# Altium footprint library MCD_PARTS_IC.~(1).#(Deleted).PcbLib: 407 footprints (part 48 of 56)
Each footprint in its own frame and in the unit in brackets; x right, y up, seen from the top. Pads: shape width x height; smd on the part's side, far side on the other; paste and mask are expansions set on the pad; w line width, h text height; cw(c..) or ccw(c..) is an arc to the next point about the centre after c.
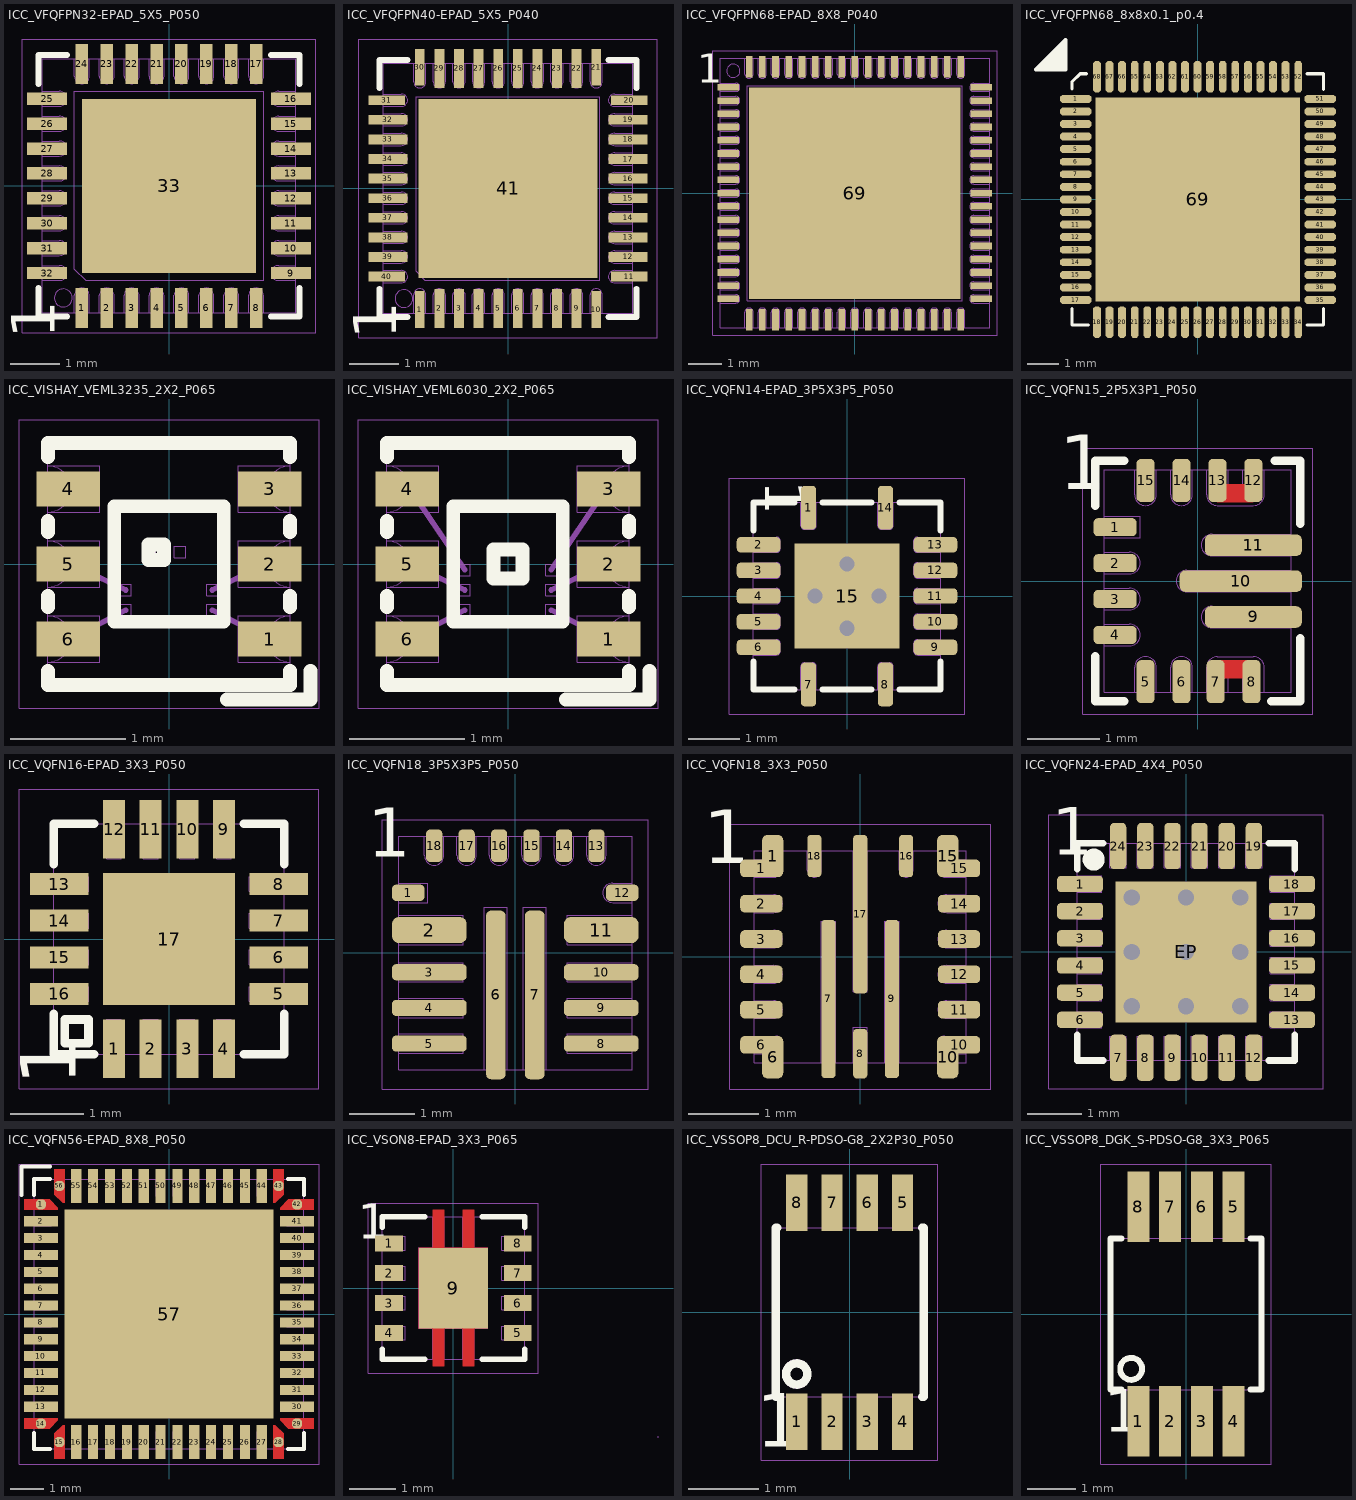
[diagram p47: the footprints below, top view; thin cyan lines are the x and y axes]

## ICC_VFQFPN32-EPAD_5X5_P050 [mm]
height 1
pads (33):
  rect 0.25x0.8 smd mask+0.05: 1(-1.75,-2.45) 2(-1.25,-2.45) 3(-0.75,-2.45) 4(-0.25,-2.45) 5(0.25,-2.45) 6(0.75,-2.45) 7(1.25,-2.45) 8(1.75,-2.45) 17(1.75,2.45) 18(1.25,2.45) 19(0.75,2.45) 20(0.25,2.45) 21(-0.25,2.45) 22(-0.75,2.45) 23(-1.25,2.45) 24(-1.75,2.45)
  rect 0.8x0.25 smd mask+0.05: 9(2.45,-1.75) 10(2.45,-1.25) 11(2.45,-0.75) 12(2.45,-0.25) 13(2.45,0.25) 14(2.45,0.75) 15(2.45,1.25) 16(2.45,1.75) 25(-2.45,1.75) 26(-2.45,1.25) 27(-2.45,0.75) 28(-2.45,0.25) 29(-2.45,-0.25) 30(-2.45,-0.75) 31(-2.45,-1.25) 32(-2.45,-1.75)
  rect 3.5x3.5 smd mask+0.05: 33(0,0)
Top Overlay:
  lines w0.12: -2.625,-2.05 -2.625,-2.625 -2.05,-2.625 ; -2.625,2.05 -2.625,2.625 -2.05,2.625 ; 2.05,-2.625 2.625,-2.625 2.625,-2.05 ; 2.05,2.625 2.625,2.625 2.625,2.05
  text "1" at -2,-3.075 h1.5
M14-Top Assembly:
  circle w0.01: c-2.125,-2.25 r0.18
  lines w0.01: -2.55,-1.9 -2.2,-1.9 ccw(c-2.2,-1.75) -2.05,-1.75 ccw(c-2.2,-1.75) -2.2,-1.6 -2.55,-1.6 ; -2.55,-1.4 -2.2,-1.4 ccw(c-2.2,-1.25) -2.05,-1.25 ccw(c-2.2,-1.25) -2.2,-1.1 -2.55,-1.1 ; -2.55,-0.9 -2.2,-0.9 ccw(c-2.2,-0.75) -2.05,-0.75 ccw(c-2.2,-0.75) -2.2,-0.6 -2.55,-0.6 ; -2.55,-0.4 -2.2,-0.4 ccw(c-2.2,-0.25) -2.05,-0.25 ccw(c-2.2,-0.25) -2.2,-0.1 -2.55,-0.1 ; -2.55,0.1 -2.2,0.1 ccw(c-2.2,0.25) -2.05,0.25 ccw(c-2.2,0.25) -2.2,0.4 -2.55,0.4 ; -2.55,0.6 -2.2,0.6 ccw(c-2.2,0.75) -2.05,0.75 ccw(c-2.2,0.75) -2.2,0.9 -2.55,0.9 ; -2.55,1.1 -2.2,1.1 ccw(c-2.2,1.25) -2.05,1.25 ccw(c-2.2,1.25) -2.2,1.4 -2.55,1.4 ; -2.55,1.6 -2.2,1.6 ccw(c-2.2,1.75) -2.05,1.75 ccw(c-2.2,1.75) -2.2,1.9 -2.55,1.9 ; -1.9,-2.55 -1.9,-2.2 cw(c-1.75,-2.2) -1.75,-2.05 cw(c-1.75,-2.2) -1.6,-2.2 -1.6,-2.55 ; -1.9,2.55 -1.9,2.2 ccw(c-1.75,2.2) -1.75,2.05 ccw(c-1.75,2.2) -1.6,2.2 -1.6,2.55 ; -1.4,-2.55 -1.4,-2.2 cw(c-1.25,-2.2) -1.25,-2.05 cw(c-1.25,-2.2) -1.1,-2.2 -1.1,-2.55 ; -1.4,2.55 -1.4,2.2 ccw(c-1.25,2.2) -1.25,2.05 ccw(c-1.25,2.2) -1.1,2.2 -1.1,2.55 ; -0.9,-2.55 -0.9,-2.2 cw(c-0.75,-2.2) -0.75,-2.05 cw(c-0.75,-2.2) -0.6,-2.2 -0.6,-2.55 ; -0.9,2.55 -0.9,2.2 ccw(c-0.75,2.2) -0.75,2.05 ccw(c-0.75,2.2) -0.6,2.2 -0.6,2.55 ; -0.4,-2.55 -0.4,-2.2 cw(c-0.25,-2.2) -0.25,-2.05 cw(c-0.25,-2.2) -0.1,-2.2 -0.1,-2.55 ; -0.4,2.55 -0.4,2.2 ccw(c-0.25,2.2) -0.25,2.05 ccw(c-0.25,2.2) -0.1,2.2 -0.1,2.55 ; 0.1,-2.55 0.1,-2.2 cw(c0.25,-2.2) 0.25,-2.05 cw(c0.25,-2.2) 0.4,-2.2 0.4,-2.55 ; 0.1,2.55 0.1,2.2 ccw(c0.25,2.2) 0.25,2.05 ccw(c0.25,2.2) 0.4,2.2 0.4,2.55 ; 0.6,-2.55 0.6,-2.2 cw(c0.75,-2.2) 0.75,-2.05 cw(c0.75,-2.2) 0.9,-2.2 0.9,-2.55 ; 0.6,2.55 0.6,2.2 ccw(c0.75,2.2) 0.75,2.05 ccw(c0.75,2.2) 0.9,2.2 0.9,2.55 ; 1.1,-2.55 1.1,-2.2 cw(c1.25,-2.2) 1.25,-2.05 cw(c1.25,-2.2) 1.4,-2.2 1.4,-2.55 ; 1.1,2.55 1.1,2.2 ccw(c1.25,2.2) 1.25,2.05 ccw(c1.25,2.2) 1.4,2.2 1.4,2.55 ; 1.6,-2.55 1.6,-2.2 cw(c1.75,-2.2) 1.75,-2.05 cw(c1.75,-2.2) 1.9,-2.2 1.9,-2.55 ; 1.6,2.55 1.6,2.2 ccw(c1.75,2.2) 1.75,2.05 ccw(c1.75,2.2) 1.9,2.2 1.9,2.55 ; 2.55,-1.9 2.2,-1.9 cw(c2.2,-1.75) 2.05,-1.75 cw(c2.2,-1.75) 2.2,-1.6 2.55,-1.6 ; 2.55,-1.4 2.2,-1.4 cw(c2.2,-1.25) 2.05,-1.25 cw(c2.2,-1.25) 2.2,-1.1 2.55,-1.1 ; 2.55,-0.9 2.2,-0.9 cw(c2.2,-0.75) 2.05,-0.75 cw(c2.2,-0.75) 2.2,-0.6 2.55,-0.6 ; 2.55,-0.4 2.2,-0.4 cw(c2.2,-0.25) 2.05,-0.25 cw(c2.2,-0.25) 2.2,-0.1 2.55,-0.1 ; 2.55,0.1 2.2,0.1 cw(c2.2,0.25) 2.05,0.25 cw(c2.2,0.25) 2.2,0.4 2.55,0.4 ; 2.55,0.6 2.2,0.6 cw(c2.2,0.75) 2.05,0.75 cw(c2.2,0.75) 2.2,0.9 2.55,0.9 ; 2.55,1.1 2.2,1.1 cw(c2.2,1.25) 2.05,1.25 cw(c2.2,1.25) 2.2,1.4 2.55,1.4 ; 2.55,1.6 2.2,1.6 cw(c2.2,1.75) 2.05,1.75 cw(c2.2,1.75) 2.2,1.9 2.55,1.9 ; -2.55,-2.55 -2.55,2.55 2.55,2.55 2.55,-2.55 -2.55,-2.55 ; -1.9,-1.67 -1.9,1.9 1.9,1.9 1.9,-1.9 -1.67,-1.9 -1.9,-1.67
  text "33" at -0.275,-0.15 h0.5
  text "32" at -2.45,-1.525 h0.5
  text "25" at -2.45,2 h0.5
  text "24" at -1.975,2.175 h0.5
  text "17" at 1.55,2.15 h0.5
  text "16" at 2.45,1.575 h0.5
  text "9" at 2.45,-1.85 h0.5
  text "8" at 1.65,-2.475 h0.5
  text "1" at -1.8,-2.475 h0.5
  text "'.Designator'" at -2,-0.5 h0.75
M16-Top Courtyard:
  lines w0.01: -2.95,-2.95 2.95,-2.95 2.95,2.95 -2.95,2.95 -2.95,-2.95
3D body "QFN32-EPAD_5X5_P050.STEP": height 0.9, standoff -0.03, extent -2.5,-2.5 2.5,2.5

## ICC_VFQFPN40-EPAD_5X5_P040 [mm]
height 1
pads (41):
  rect 0.2x0.75 smd mask+0.05: 1(-1.8,-2.475) 10(1.8,-2.475) 21(1.8,2.475) 30(-1.8,2.475)
  rect 0.2x0.8 smd mask+0.05: 2(-1.4,-2.45) 3(-1,-2.45) 4(-0.6,-2.45) 5(-0.2,-2.45) 6(0.2,-2.45) 7(0.6,-2.45) 8(1,-2.45) 9(1.4,-2.45) 22(1.4,2.45) 23(1,2.45) 24(0.6,2.45) 25(0.2,2.45) 26(-0.2,2.45) 27(-0.6,2.45) 28(-1,2.45) 29(-1.4,2.45)
  rect 0.75x0.2 smd mask+0.05: 11(2.475,-1.8) 20(2.475,1.8) 31(-2.475,1.8) 40(-2.475,-1.8)
  rect 0.8x0.2 smd mask+0.05: 12(2.45,-1.4) 13(2.45,-1) 14(2.45,-0.6) 15(2.45,-0.2) 16(2.45,0.2) 17(2.45,0.6) 18(2.45,1) 19(2.45,1.4) 32(-2.45,1.4) 33(-2.45,1) 34(-2.45,0.6) 35(-2.45,0.2) 36(-2.45,-0.2) 37(-2.45,-0.6) 38(-2.45,-1) 39(-2.45,-1.4)
  rect 3.65x3.65 smd mask+0.05: 41(0,0)
Top Overlay:
  lines w0.12: -2.625,-2.05 -2.625,-2.625 -2.05,-2.625 ; -2.625,2.05 -2.625,2.625 -2.05,2.625 ; 2.05,-2.625 2.625,-2.625 2.625,-2.05 ; 2.05,2.625 2.625,2.625 2.625,2.05
  text "1" at -2,-3.075 h1.5
M14-Top Assembly:
  drawing of 170 lines, arcs and shapes, not listed
  text "31" at -2.45,2 h0.5
  text "'.Designator'" at -2,-0.5 h0.75
  text "1" at -1.85,-2.475 h0.5
  text "10" at 1.55,-2.475 h0.5
  text "11" at 2.475,-2 h0.5
  text "20" at 2.45,1.575 h0.5
  text "21" at 1.6,2.15 h0.5
  text "30" at -2.05,2.175 h0.5
  text "40" at -2.475,-1.55 h0.5
  text "41" at -0.275,-0.15 h0.5
M16-Top Courtyard:
  lines w0.01: -3.05,-3.05 -3.05,3.05 3.05,3.05 3.05,-3.05 -3.05,-3.05
3D body "User Library-QFN40_500_500_090_360P040.STEP": height 0.9, standoff 0, extent -2.505,-2.505 2.505,2.505

## ICC_VFQFPN68-EPAD_8X8_P040 [mm]
height 1
pads (69):
  rect 0.65x0.2 smd mask+0.05: 1(-3.825,3.2) 2(-3.825,2.8) 3(-3.825,2.4) 4(-3.825,2) 5(-3.825,1.6) 6(-3.825,1.2) 7(-3.825,0.8) 8(-3.825,0.4) 9(-3.825,0) 10(-3.825,-0.4) 11(-3.825,-0.8) 12(-3.825,-1.2) 13(-3.825,-1.6) 14(-3.825,-2) 15(-3.825,-2.4) 16(-3.825,-2.8) 17(-3.825,-3.2) 35(3.825,-3.2) 36(3.825,-2.8) 37(3.825,-2.4) 38(3.825,-2) 39(3.825,-1.6) 40(3.825,-1.2) 41(3.825,-0.8) 42(3.825,-0.4) 43(3.825,0) 44(3.825,0.4) 45(3.825,0.8) 46(3.825,1.2) 47(3.825,1.6) 48(3.825,2) 49(3.825,2.4) 50(3.825,2.8) 51(3.825,3.2)
  rect 0.2x0.65 smd mask+0.05: 18(-3.2,-3.825) 19(-2.8,-3.825) 20(-2.4,-3.825) 21(-2,-3.825) 22(-1.6,-3.825) 23(-1.2,-3.825) 24(-0.8,-3.825) 25(-0.4,-3.825) 26(0,-3.825) 27(0.4,-3.825) 28(0.8,-3.825) 29(1.2,-3.825) 30(1.6,-3.825) 31(2,-3.825) 32(2.4,-3.825) 33(2.8,-3.825) 34(3.2,-3.825) 52(3.2,3.825) 53(2.8,3.825) 54(2.4,3.825) 55(2,3.825) 56(1.6,3.825) 57(1.2,3.825) 58(0.8,3.825) 59(0.4,3.825) 60(0,3.825) 61(-0.4,3.825) 62(-0.8,3.825) 63(-1.2,3.825) 64(-1.6,3.825) 65(-2,3.825) 66(-2.4,3.825) 67(-2.8,3.825) 68(-3.2,3.825)
  rect 6.4x6.4 smd mask+0.05: 69(0,0)
Top Overlay:
  text "1" at -4.775,3.05 h1.5
M14-Top Assembly:
  drawing of 281 lines, arcs and shapes, not listed
  text "69" at -0.325,-0.2 h0.65
  text "1" at -3.837,3.075 h0.65
  text "17" at -3.975,-3.45 h0.65
  text "34" at 2.9,-4 h0.65
  text "18" at -3.55,-3.975 h0.65
  text "'.Designator'" at -2,0 h0.75
  text "35" at 3.425,-3.425 h0.65
  text "51" at 3.425,3 h0.65
  text "52" at 2.925,3.6 h0.65
  text "68" at -3.475,3.55 h0.65
M16-Top Courtyard:
  lines w0.01: -4.3,-4.3 -4.3,4.3 4.3,4.3 4.3,-4.3 -4.3,-4.3
3D body: height 1, standoff 0, extent -4.075,-4.075 4.075,4.075
3D body: height 1.1, standoff 1, extent -3.873,3.5 -3.475,3.9

## ICC_VFQFPN68_8x8x0.1_p0.4 [mm]
pads (69):
  oct 1x0.25 smd mask+0.04: 1(-3.878,3.2) 2(-3.878,2.8) 3(-3.878,2.4) 4(-3.878,2) 5(-3.878,1.6) 6(-3.878,1.2) 7(-3.878,0.8) 8(-3.878,0.4) 9(-3.878,0) 10(-3.878,-0.4) 11(-3.878,-0.8) 12(-3.878,-1.2) 13(-3.878,-1.6) 14(-3.878,-2) 15(-3.878,-2.4) 16(-3.878,-2.8) 17(-3.878,-3.2) 35(3.903,-3.2) 36(3.903,-2.8) 37(3.903,-2.4) 38(3.903,-2) 39(3.903,-1.6) 40(3.903,-1.2) 41(3.903,-0.8) 42(3.903,-0.4) 43(3.903,0) 44(3.903,0.4) 45(3.903,0.8) 46(3.903,1.2) 47(3.903,1.6) 48(3.903,2) 49(3.903,2.4) 50(3.903,2.8) 51(3.903,3.2)
  oct 0.25x1 smd mask+0.04: 18(-3.2,-3.903) 19(-2.8,-3.903) 20(-2.4,-3.903) 21(-2,-3.903) 22(-1.6,-3.903) 23(-1.2,-3.903) 24(-0.8,-3.903) 25(-0.4,-3.903) 26(0,-3.903) 27(0.4,-3.903) 28(0.8,-3.903) 29(1.2,-3.903) 30(1.6,-3.903) 31(2,-3.903) 32(2.4,-3.903) 33(2.8,-3.903) 34(3.2,-3.903) 52(3.2,3.903) 53(2.8,3.903) 54(2.4,3.903) 55(2,3.903) 56(1.6,3.903) 57(1.2,3.903) 58(0.8,3.903) 59(0.4,3.903) 60(0,3.903) 61(-0.4,3.903) 62(-0.8,3.903) 63(-1.2,3.903) 64(-1.6,3.903) 65(-2,3.903) 66(-2.4,3.903) 67(-2.8,3.903) 68(-3.2,3.903)
  rect 6.5x6.5 smd paste-5 mask-0.01: 69(0,0)
Top Overlay:
  lines w0.1: -4,-3.467 -4,-4 -3.48,-4 ; -4,3.518 -4,3.734 -3.734,4 -3.531,4 ; 3.48,-4 4,-4 4,-3.467 ; 3.48,4 4,4 4,3.493
  lines w0.127: -4.451,4.613 -5.141,4.126 ; -5.141,4.126 -4.201,4.126 ; -5.141,4.126 -4.201,5.066 ; -4.201,4.126 -4.201,5.066 ; -4.201,4.126 -4.43,4.126 -4.201,4.355 -4.201,4.482 -4.557,4.126 -4.658,4.126 -4.201,4.584 -4.201,4.711 -4.785,4.126 -4.938,4.126 -4.201,4.863 -4.201,5.066 ; -4.201,4.126 -4.573,4.491 -4.201,5.066
Top Paste:
  rectangle: -2.979,1.168 -1.219,2.928
  rectangle: -0.846,1.194 0.914,2.954
  rectangle: 1.219,1.194 2.979,2.954
  rectangle: 1.212,-0.871 2.972,0.889
  rectangle: -0.88,-0.88 0.88,0.88
  rectangle: -3.005,-0.88 -1.245,0.88
  rectangle: 1.212,-2.946 2.972,-1.186
  rectangle: -0.871,-2.921 0.889,-1.161
  rectangle: -3.005,-2.921 -1.245,-1.161
3D body: height 1.1, standoff 0, extent -4.013,-3.988 3.988,3.988
3D body: height 1.2, standoff 1.1, extent -3.703,3.002 -3.103,3.602

## ICC_VISHAY_VEML3235_2X2_P065 [mm] "MCD-03497"
height 0.87
pads (6):
  rect 0.55x0.3 smd mask+0.05: 1(0.875,-0.65) 2(0.875,0) 3(0.875,0.65) 4(-0.875,0.65) 5(-0.875,0) 6(-0.875,-0.65)
Top Overlay:
  lines w0.12: -1.05,-0.925 -1.05,-1.05 1.05,-1.05 1.05,-0.925 ; -1.05,-0.375 -1.05,-0.275 ; -1.05,0.275 -1.05,0.375 ; -1.05,0.925 -1.05,1.05 1.05,1.05 1.05,0.925 ; 0.5,-1.175 1.225,-1.175 1.225,-0.925 ; 1.05,-0.375 1.05,-0.275 ; 1.05,0.275 1.05,0.375 ; -0.475,-0.5 0.475,-0.5 0.475,0.5 -0.475,0.5 -0.475,-0.5 ; -0.178,0.035 -0.178,0.17 -0.042,0.17 -0.042,0.035 -0.178,0.035
M14-Top Assembly:
  lines w0.01: -1.05,-1.05 -1.05,1.05 1.05,1.05 1.05,-1.05 -1.05,-1.05 ; -1.05,-0.85 ccw(c-1.05,-0.65) -0.85,-0.65 ccw(c-1.05,-0.65) -1.05,-0.45 -0.6,-0.45 -0.6,-0.85 -1.05,-0.85 ; -1.05,-0.2 ccw(c-1.05,0) -0.85,0 ccw(c-1.05,0) -1.05,0.2 -0.6,0.2 -0.6,-0.2 -1.05,-0.2 ; -1.05,0.45 ccw(c-1.05,0.65) -0.85,0.65 ccw(c-1.05,0.65) -1.05,0.85 -0.6,0.85 -0.6,0.45 -1.05,0.45 ; -0.5,-0.5 0.5,-0.5 0.5,0.5 -0.5,0.5 -0.5,-0.5 ; -0.425,-0.45 -0.425,-0.425 -0.425,-0.35 -0.325,-0.35 -0.325,-0.45 -0.425,-0.45 ; -0.425,-0.275 -0.425,-0.25 -0.425,-0.175 -0.325,-0.175 -0.325,-0.275 -0.425,-0.275 ; -0.215,0.055 -0.215,0.08 -0.215,0.155 -0.115,0.155 -0.115,0.055 -0.215,0.055 ; -0.085,0.055 -0.085,0.08 -0.085,0.155 0.015,0.155 0.015,0.055 -0.085,0.055 ; 0.045,0.055 0.045,0.08 0.045,0.155 0.145,0.155 0.145,0.055 0.045,0.055 ; 0.325,-0.45 0.325,-0.425 0.325,-0.35 0.425,-0.35 0.425,-0.45 0.325,-0.45 ; 0.325,-0.275 0.325,-0.25 0.325,-0.175 0.425,-0.175 0.425,-0.275 0.325,-0.275 ; 0.6,-0.85 1.05,-0.85 cw(c1.05,-0.65) 0.85,-0.65 cw(c1.05,-0.65) 1.05,-0.45 0.6,-0.45 0.6,-0.85 ; 0.6,-0.2 1.05,-0.2 cw(c1.05,0) 0.85,0 cw(c1.05,0) 1.05,0.2 0.6,0.2 0.6,-0.2 ; 0.6,0.45 1.05,0.45 cw(c1.05,0.65) 0.85,0.65 cw(c1.05,0.65) 1.05,0.85 0.6,0.85 0.6,0.45
  lines w0.05: -0.85,-0.65 -0.375,-0.4 ; -0.85,0 -0.375,-0.225 ; 0.375,-0.4 0.85,-0.65 ; 0.375,-0.225 0.85,0
  text "'.Designator'" at -2,-0.5 h0.75
  text "1" at 0.735,-0.84 h0.6
  text "2" at 0.735,-0.19 h0.6
  text "3" at 0.735,0.46 h0.6
  text "4" at -0.965,0.455 h0.6
  text "5" at -0.965,-0.195 h0.6
  text "6" at -0.965,-0.845 h0.6
  text "NC" at -0.65,0.58 h0.35
  text "NC" at 0.285,0.58 h0.35
M16-Top Courtyard:
  lines w0.01: -1.3,-1.25 1.3,-1.25 1.3,1.25 -1.3,1.25 -1.3,-1.25
3D body "VEML6030.stp": height 0.87, standoff 0, extent -1,-1 1,1

## ICC_VISHAY_VEML6030_2X2_P065 [mm] "MCD-02336"
height 0.87
pads (6):
  rect 0.55x0.3 smd mask+0.05: 1(0.875,-0.65) 2(0.875,0) 3(0.875,0.65) 4(-0.875,0.65) 5(-0.875,0) 6(-0.875,-0.65)
Top Overlay:
  lines w0.12: -1.05,-0.925 -1.05,-1.05 1.05,-1.05 1.05,-0.925 ; -1.05,-0.375 -1.05,-0.275 ; -1.05,0.275 -1.05,0.375 ; -1.05,0.925 -1.05,1.05 1.05,1.05 1.05,0.925 ; 0.5,-1.175 1.225,-1.175 1.225,-0.925 ; 1.05,-0.375 1.05,-0.275 ; 1.05,0.275 1.05,0.375 ; -0.475,-0.5 0.475,-0.5 0.475,0.5 -0.475,0.5 -0.475,-0.5 ; -0.125,-0.125 -0.125,0.125 0.125,0.125 0.125,-0.125 -0.125,-0.125
M14-Top Assembly:
  lines w0.01: -1.05,-1.05 -1.05,1.05 1.05,1.05 1.05,-1.05 -1.05,-1.05 ; -1.05,-0.85 ccw(c-1.05,-0.65) -0.85,-0.65 ccw(c-1.05,-0.65) -1.05,-0.45 -0.6,-0.45 -0.6,-0.85 -1.05,-0.85 ; -1.05,-0.2 ccw(c-1.05,0) -0.85,0 ccw(c-1.05,0) -1.05,0.2 -0.6,0.2 -0.6,-0.2 -1.05,-0.2 ; -1.05,0.45 ccw(c-1.05,0.65) -0.85,0.65 ccw(c-1.05,0.65) -1.05,0.85 -0.6,0.85 -0.6,0.45 -1.05,0.45 ; -0.5,-0.5 0.5,-0.5 0.5,0.5 -0.5,0.5 -0.5,-0.5 ; -0.425,-0.45 -0.425,-0.425 -0.425,-0.35 -0.325,-0.35 -0.325,-0.45 -0.425,-0.45 ; -0.425,-0.275 -0.425,-0.25 -0.425,-0.175 -0.325,-0.175 -0.325,-0.275 -0.425,-0.275 ; -0.425,-0.1 -0.425,-0.075 -0.425,0 -0.325,0 -0.325,-0.1 -0.425,-0.1 ; -0.125,-0.125 -0.125,0.125 0.125,0.125 0.125,-0.125 -0.125,-0.125 ; 0.325,-0.45 0.325,-0.425 0.325,-0.35 0.425,-0.35 0.425,-0.45 0.325,-0.45 ; 0.325,-0.275 0.325,-0.25 0.325,-0.175 0.425,-0.175 0.425,-0.275 0.325,-0.275 ; 0.325,-0.1 0.325,-0.075 0.325,0 0.425,0 0.425,-0.1 0.325,-0.1 ; 0.6,-0.85 1.05,-0.85 cw(c1.05,-0.65) 0.85,-0.65 cw(c1.05,-0.65) 1.05,-0.45 0.6,-0.45 0.6,-0.85 ; 0.6,-0.2 1.05,-0.2 cw(c1.05,0) 0.85,0 cw(c1.05,0) 1.05,0.2 0.6,0.2 0.6,-0.2 ; 0.6,0.45 1.05,0.45 cw(c1.05,0.65) 0.85,0.65 cw(c1.05,0.65) 1.05,0.85 0.6,0.85 0.6,0.45
  lines w0.05: -0.85,-0.65 -0.375,-0.4 ; -0.85,0 -0.375,-0.225 ; -0.85,0.65 -0.375,-0.05 ; 0.375,-0.4 0.85,-0.65 ; 0.375,-0.225 0.85,0 ; 0.375,-0.05 0.85,0.65
  text "'.Designator'" at -2,0.225 h0.75
  text "1" at 1.025,-0.725 h0.6
  text "2" at 1.025,-0.125 h0.6
  text "3" at 1.025,0.525 h0.6
  text "4" at -0.65,0.525 h0.6
  text "5" at -0.65,-0.125 h0.6
  text "6" at -0.65,-0.775 h0.6
M16-Top Courtyard:
  lines w0.01: -1.3,-1.25 1.3,-1.25 1.3,1.25 -1.3,1.25 -1.3,-1.25
3D body "VEML6030.stp": height 0.87, standoff 0, extent -1,-1 1,1

## ICC_VQFN14-EPAD_3P5X3P5_P050 [mm] "MCD-01489"
height 1
pads (15):
  rrect50% 0.3x0.85 smd mask+0.05: 1(-0.75,1.725) 7(-0.75,-1.725) 8(0.75,-1.725) 14(0.75,1.725)
  rrect50% 0.85x0.3 smd mask+0.05: 2(-1.725,1) 3(-1.725,0.5) 4(-1.725,0) 5(-1.725,-0.5) 6(-1.725,-1) 9(1.725,-1) 10(1.725,-0.5) 11(1.725,0) 12(1.725,0.5) 13(1.725,1)
  rect 2.05x2.05 smd paste-10 mask+0.05: 15(0,0)
via 0.625,0 diameter 0.6 hole 0.3
via 0,-0.625 diameter 0.6 hole 0.3
via -0.625,0 diameter 0.6 hole 0.3
via 0,0.625 diameter 0.6 hole 0.3
Top Overlay:
  lines w0.12: -1.825,-1.275 -1.825,-1.825 -1.025,-1.825 ; -1.825,1.275 -1.825,1.825 -1.025,1.825 ; -0.475,-1.825 0.475,-1.825 ; -0.475,1.825 0.475,1.825 ; 1.025,-1.825 1.825,-1.825 1.825,-1.275 ; 1.025,1.825 1.825,1.825 1.825,1.275
  text "1" at -1.85,2.25 h1.3
Top Paste:
  rectangle: 0.1,0.1 0.925,0.925
  rectangle: 0.1,-0.925 0.925,-0.1
  rectangle: -0.925,-0.925 -0.1,-0.1
  rectangle: -0.925,0.1 -0.1,0.925
M14-Top Assembly:
  lines w0.01: -1.825,-1.15 -1.375,-1.15 ccw(c-1.375,-1.075) -1.3,-1.075 -1.3,-0.925 ccw(c-1.375,-0.925) -1.375,-0.85 -1.825,-0.85 ; -1.825,-0.65 -1.375,-0.65 ccw(c-1.375,-0.575) -1.3,-0.575 -1.3,-0.425 ccw(c-1.375,-0.425) -1.375,-0.35 -1.825,-0.35 ; -1.825,-0.15 -1.375,-0.15 ccw(c-1.375,-0.075) -1.3,-0.075 -1.3,0.075 ccw(c-1.375,0.075) -1.375,0.15 -1.825,0.15 ; -1.825,0.35 -1.375,0.35 ccw(c-1.375,0.425) -1.3,0.425 -1.3,0.575 ccw(c-1.375,0.575) -1.375,0.65 -1.825,0.65 ; -1.825,0.85 -1.375,0.85 ccw(c-1.375,0.925) -1.3,0.925 -1.3,1.075 ccw(c-1.375,1.075) -1.375,1.15 -1.825,1.15 ; -0.9,-1.825 -0.9,-1.375 cw(c-0.825,-1.375) -0.825,-1.3 -0.675,-1.3 cw(c-0.675,-1.375) -0.6,-1.375 -0.6,-1.825 ; -0.9,1.825 -0.9,1.375 ccw(c-0.825,1.375) -0.825,1.3 -0.675,1.3 ccw(c-0.675,1.375) -0.6,1.375 -0.6,1.825 ; 0.6,-1.825 0.6,-1.375 cw(c0.675,-1.375) 0.675,-1.3 0.825,-1.3 cw(c0.825,-1.375) 0.9,-1.375 0.9,-1.825 ; 0.6,1.825 0.6,1.375 ccw(c0.675,1.375) 0.675,1.3 0.825,1.3 ccw(c0.825,1.375) 0.9,1.375 0.9,1.825 ; 1.825,-1.15 1.375,-1.15 cw(c1.375,-1.075) 1.3,-1.075 1.3,-0.925 cw(c1.375,-0.925) 1.375,-0.85 1.825,-0.85 ; 1.825,-0.65 1.375,-0.65 cw(c1.375,-0.575) 1.3,-0.575 1.3,-0.425 cw(c1.375,-0.425) 1.375,-0.35 1.825,-0.35 ; 1.825,-0.15 1.375,-0.15 cw(c1.375,-0.075) 1.3,-0.075 1.3,0.075 cw(c1.375,0.075) 1.375,0.15 1.825,0.15 ; 1.825,0.35 1.375,0.35 cw(c1.375,0.425) 1.3,0.425 1.3,0.575 cw(c1.375,0.575) 1.375,0.65 1.825,0.65 ; 1.825,0.85 1.375,0.85 cw(c1.375,0.925) 1.3,0.925 1.3,1.075 cw(c1.375,1.075) 1.375,1.15 1.825,1.15 ; -1.825,-1.825 1.825,-1.825 1.825,1.825 -1.825,1.825 -1.825,-1.825 ; -1,-1 1,-1 1,1 -1,1 -1,-1
  text "15" at -0.3,-0.225 h0.7
  text "14" at 0.45,1.325 h0.7
  text "13" at 1.775,0.725 h0.7
  text "9" at 1.775,-1.15 h0.7
  text "'.Designator'" at -2,0.25 h0.75
  text "1" at -0.85,1.325 h0.7
  text "2" at -1.775,1.15 h0.7
  text "6" at -1.775,-0.85 h0.7
  text "7" at -0.9,-1.775 h0.7
  text "8" at 0.6,-1.775 h0.7
M16-Top Courtyard:
  lines w0.01: -2.3,-2.3 -1.625,-2.3 2.3,-2.3 2.3,2.3 -0.975,2.3 -2.3,2.3 -2.3,-2.3
3D body: height 1, standoff 0, extent -1.825,-1.825 1.825,1.825
3D body: height 1.01, standoff 1, extent -1.725,1.225 -1.225,1.725

## ICC_VQFN15_2P5X3P1_P050 [mm]
height 1
pads (15):
  rrect50% 0.6x0.25 smd mask+0.05: 1(-1.15,0.75) 2(-1.15,0.25) 3(-1.15,-0.25) 4(-1.15,-0.75)
  rrect50% 0.25x0.6 smd mask+0.05: 5(-0.725,-1.4) 6(-0.225,-1.4) 7(0.25,-1.4) 8(0.75,-1.4) 12(0.775,1.4) 13(0.275,1.4) 14(-0.225,1.4) 15(-0.725,1.4)
  rrect50% 1.35x0.3 smd mask+0.05: 9(0.775,-0.5) 11(0.775,0.5)
  rrect50% 1.7x0.3 smd mask+0.05: 10(0.6,0)
Top Layer:
  region: 0.775,1.1 0.275,1.1 0.275,1.35 0.775,1.35 0.775,1.2
  region: 0.25,-1.1 0.75,-1.1 0.75,-1.35 0.25,-1.35 0.25,-1.2
Top Overlay:
  lines w0.12: -1.425,-1.05 -1.425,-1.675 -1.3,-1.675 -1.025,-1.675 ; -1.425,1.05 -1.425,1.675 -1.3,1.675 -1.025,1.675 ; 1.025,-1.675 1.425,-1.675 1.425,-1.575 1.425,-0.8 ; 1.075,1.675 1.425,1.675 1.425,1.575 1.425,0.8
  text "1" at -1.925,1.025 h1.3
M14-Top Assembly:
  lines w0.01: -1.3,-0.9 -0.95,-0.9 ccw(c-0.95,-0.75) -0.8,-0.75 ccw(c-0.95,-0.75) -0.95,-0.6 -1.3,-0.6 ; -1.3,-0.4 -0.95,-0.4 ccw(c-0.95,-0.25) -0.8,-0.25 ccw(c-0.95,-0.25) -0.95,-0.1 -1.3,-0.1 ; -1.3,0.1 -0.95,0.1 ccw(c-0.95,0.25) -0.8,0.25 ccw(c-0.95,0.25) -0.95,0.4 -1.3,0.4 ; -1.3,0.6 -0.8,0.6 -0.8,0.9 -1.3,0.9 ; -0.875,-1.55 -0.875,-1.2 cw(c-0.725,-1.2) -0.725,-1.05 cw(c-0.725,-1.2) -0.575,-1.2 -0.575,-1.55 ; -0.875,1.55 -0.875,1.2 ccw(c-0.725,1.2) -0.725,1.05 ccw(c-0.725,1.2) -0.575,1.2 -0.575,1.55 ; -0.375,-1.55 -0.375,-1.2 cw(c-0.225,-1.2) -0.225,-1.05 cw(c-0.225,-1.2) -0.075,-1.2 -0.075,-1.55 ; -0.375,1.55 -0.375,1.2 ccw(c-0.225,1.2) -0.225,1.05 ccw(c-0.225,1.2) -0.075,1.2 -0.075,1.55 ; 0.125,-1.55 0.125,-1.2 cw(c0.275,-1.2) 0.275,-1.05 0.775,-1.05 cw(c0.775,-1.2) 0.925,-1.2 0.925,-1.55 ; 0.125,1.55 0.125,1.2 ccw(c0.275,1.2) 0.275,1.05 0.775,1.05 ccw(c0.775,1.2) 0.925,1.2 0.925,1.55 ; 0.425,-1.55 0.425,-1.3 0.625,-1.3 0.625,-1.55 ; 0.425,1.55 0.425,1.3 0.625,1.3 0.625,1.55 ; 1.3,-0.65 0.2,-0.65 cw(c0.2,-0.5) 0.05,-0.5 cw(c0.2,-0.5) 0.2,-0.35 1.3,-0.35 ; 1.3,-0.15 -0.15,-0.15 cw(c-0.15,0) -0.3,0 cw(c-0.15,0) -0.15,0.15 1.3,0.15 ; 1.3,0.35 0.2,0.35 cw(c0.2,0.5) 0.05,0.5 cw(c0.2,0.5) 0.2,0.65 1.3,0.65 ; -1.3,-1.55 -1.3,1.55 1.3,1.55 1.3,-1.55 -1.3,-1.55
  text "5" at -0.825,-1.475 h0.4
  text "'.Designator'" at -2,-0.5 h0.75
  text "15" at -0.9,1.225 h0.4
  text "12" at 0.6,1.225 h0.4
  text "11" at 0.6,0.375 h0.4
  text "9" at 0.675,-0.625 h0.4
  text "8" at 0.7,-1.475 h0.4
  text "4" at -1.175,-0.875 h0.4
  text "1" at -1.125,0.625 h0.4
M16-Top Courtyard:
  lines w0.01: -1.6,-1.85 -1.6,1.85 1.6,1.85 1.6,-1.85 -1.6,-1.85
3D body: height 1.01, standoff 1, extent -1.12,0.966 -0.72,1.366
3D body: height 1, standoff 0, extent -1.3,-1.55 1.3,1.55

## ICC_VQFN16-EPAD_3X3_P050 [mm] "MCD-02580"
height 1
pads (17):
  rect 0.3x0.8 smd mask+0.05: 1(-0.75,-1.5) 2(-0.25,-1.5) 3(0.25,-1.5) 4(0.75,-1.5) 9(0.75,1.5) 10(0.25,1.5) 11(-0.25,1.5) 12(-0.75,1.5)
  rect 0.8x0.3 smd mask+0.05: 5(1.5,-0.75) 6(1.5,-0.25) 7(1.5,0.25) 8(1.5,0.75) 13(-1.5,0.75) 14(-1.5,0.25) 15(-1.5,-0.25) 16(-1.5,-0.75)
  rect 1.8x1.8 smd mask+0.05: 17(0,0)
Top Overlay:
  lines w0.12: -1.575,-1.025 -1.575,-1.575 -1.55,-1.575 -1.025,-1.575 ; -1.575,1.025 -1.575,1.575 -1.025,1.575 ; 1.025,-1.575 1.575,-1.575 1.575,-1.025 ; 1.025,1.575 1.575,1.575 1.575,1.025 ; -1.425,-1.425 -1.425,-1.1 -1.1,-1.1 -1.1,-1.425 -1.425,-1.425
  text "1" at -1.025,-2 h1.3
M14-Top Assembly:
  lines w0.01: -1.575,-0.85 -1.1,-0.85 -1.1,-0.65 -1.575,-0.65 ; -1.575,-0.35 -1.1,-0.35 -1.1,-0.15 -1.575,-0.15 ; -1.575,0.15 -1.1,0.15 -1.1,0.35 -1.575,0.35 ; -1.575,0.65 -1.1,0.65 -1.1,0.85 -1.575,0.85 ; -0.85,-1.575 -0.85,-1.1 -0.65,-1.1 -0.65,-1.575 ; -0.85,1.575 -0.85,1.1 -0.65,1.1 -0.65,1.575 ; -0.35,-1.575 -0.35,-1.1 -0.15,-1.1 -0.15,-1.575 ; -0.35,1.575 -0.35,1.1 -0.15,1.1 -0.15,1.575 ; 0.15,-1.575 0.15,-1.1 0.35,-1.1 0.35,-1.575 ; 0.15,1.575 0.15,1.1 0.35,1.1 0.35,1.575 ; 0.65,-1.575 0.65,-1.1 0.85,-1.1 0.85,-1.575 ; 0.65,1.575 0.65,1.1 0.85,1.1 0.85,1.575 ; 1.575,-0.85 1.1,-0.85 1.1,-0.65 1.575,-0.65 ; 1.575,-0.35 1.1,-0.35 1.1,-0.15 1.575,-0.15 ; 1.575,0.15 1.1,0.15 1.1,0.35 1.575,0.35 ; 1.575,0.65 1.1,0.65 1.1,0.85 1.575,0.85 ; -1.575,-1.575 1.575,-1.575 1.575,1.575 -1.575,1.575 -1.575,-1.575 ; -1.425,-1.425 -1.425,-1.1 -1.1,-1.1 -1.1,-1.425 -1.425,-1.425 ; -0.85,-0.85 -0.85,0.85 0.85,0.85 0.85,-0.85 -0.85,-0.85
  text "1" at -0.805,-1.449 h0.4
  text "4" at 0.66,-1.449 h0.4
  text "5" at 1.25,-0.875 h0.4
  text "8" at 1.25,0.625 h0.4
  text "9" at 0.671,1.177 h0.4
  text "12" at -0.925,1.175 h0.4
  text "13" at -1.503,0.628 h0.4
  text "16" at -1.507,-0.874 h0.4
  text "17" at -0.15,-0.125 h0.4
  text "'.Designator'" at 0,0 h0.75
M16-Top Courtyard:
  lines w0.01: -2.05,-2.05 2.05,-2.05 2.05,2.05 -2.05,2.05 -2.05,-2.05
3D body "QFN16-EPAD_3X3_P050.STEP": height 0.9, standoff 0, extent -1.501,-1.501 1.501,1.501
3D body: height 1, standoff 0, extent -1.575,-1.575 1.575,1.575

## ICC_VQFN18_3P5X3P5_P050 [mm] "MCD-03082"
height 1
pads (18):
  rrect50% 0.5x0.25 smd mask+0.05: 1(-1.65,0.925) 12(1.65,0.925)
  rrect50% 1.15x0.4 smd mask+0.05: 2(-1.325,0.35) 11(1.325,0.35)
  rrect50% 1.15x0.25 smd mask+0.05: 3(-1.325,-0.3) 4(-1.325,-0.85) 5(-1.325,-1.4) 8(1.325,-1.4) 9(1.325,-0.85) 10(1.325,-0.3)
  rrect50% 0.3x2.6 smd mask+0.05: 6(-0.3,-0.65) 7(0.3,-0.65)
  rrect50% 0.25x0.5 smd mask+0.05: 13(1.25,1.65) 14(0.75,1.65) 15(0.25,1.65) 16(-0.25,1.65) 17(-0.75,1.65) 18(-1.25,1.65)
Top Overlay:
  text "1" at -2.275,1.225 h1.3
M14-Top Assembly:
  lines w0.01: -1.8,-1.55 -0.8,-1.55 -0.8,-1.25 -1.8,-1.25 ; -1.8,-1 -0.8,-1 -0.8,-0.7 -1.8,-0.7 ; -1.8,-0.45 -0.8,-0.45 -0.8,-0.15 -1.8,-0.15 ; -1.8,0.125 -0.8,0.125 -0.8,0.575 -1.8,0.575 ; -1.8,0.775 -1.35,0.775 -1.35,1.075 -1.8,1.075 ; -1.4,1.8 -1.4,1.5 ccw(c-1.25,1.5) -1.25,1.35 ccw(c-1.25,1.5) -1.1,1.5 -1.1,1.8 ; -0.9,1.8 -0.9,1.5 ccw(c-0.75,1.5) -0.75,1.35 ccw(c-0.75,1.5) -0.6,1.5 -0.6,1.8 ; -0.475,-1.8 -0.475,0.7 -0.125,0.7 -0.125,-1.8 ; -0.4,1.8 -0.4,1.5 ccw(c-0.25,1.5) -0.25,1.35 ccw(c-0.25,1.5) -0.1,1.5 -0.1,1.8 ; 0.1,1.8 0.1,1.5 ccw(c0.25,1.5) 0.25,1.35 ccw(c0.25,1.5) 0.4,1.5 0.4,1.8 ; 0.125,-1.8 0.125,0.7 0.475,0.7 0.475,-1.8 ; 0.6,1.8 0.6,1.5 ccw(c0.75,1.5) 0.75,1.35 ccw(c0.75,1.5) 0.9,1.5 0.9,1.8 ; 1.1,1.8 1.1,1.5 ccw(c1.25,1.5) 1.25,1.35 ccw(c1.25,1.5) 1.4,1.5 1.4,1.8 ; 1.8,-1.55 0.8,-1.55 0.8,-1.25 1.8,-1.25 ; 1.8,-1 0.8,-1 0.8,-0.7 1.8,-0.7 ; 1.8,-0.45 0.8,-0.45 0.8,-0.15 1.8,-0.15 ; 1.8,0.125 0.8,0.125 0.8,0.575 1.8,0.575 ; 1.8,0.775 1.5,0.775 cw(c1.5,0.925) 1.35,0.925 cw(c1.5,0.925) 1.5,1.075 1.8,1.075 ; -1.8,1.8 -1.8,-1.8 1.8,-1.8 1.8,1.8 ; -1.8,1.8 1.8,1.8 ; -1.8,1.8 1.8,1.8
  text "18" at -1.425,1.475 h0.4
  text "12" at 1.425,0.8 h0.4
  text "6" at -0.375,-1.725 h0.4
  text "7" at 0.225,-1.725 h0.4
  text "'.Designator'" at -2,-0.5 h0.75
  text "13" at 1.075,1.475 h0.4
  text "5" at -1.4,-1.525 h0.4
  text "1" at -1.625,0.8 h0.4
  text "8" at 1.4,-1.525 h0.4
M16-Top Courtyard:
  lines w0.01: -2.05,-2.1 -2.05,2.05 2.05,2.05 2.05,-2.1 -2.05,-2.1
3D body: height 1, standoff 0, extent -1.8,-1.8 1.8,1.8
3D body: height 1.01, standoff 1, extent -1.624,1.275 -1.226,1.675

## ICC_VQFN18_3X3_P050 [mm] "MCD-02369"
height 1
pads (22):
  rrect50% 0.6x0.25 smd mask+0.05: 1(-1.4,1.25) 2(-1.4,0.75) 3(-1.4,0.25) 4(-1.4,-0.25) 5(-1.4,-0.75) 6(-1.4,-1.25) 10(1.4,-1.25) 11(1.4,-0.75) 12(1.4,-0.25) 13(1.4,0.25) 14(1.4,0.75) 15(1.4,1.25)
  rrect50% 0.3x0.6 smd mask+0.05: 1(-1.24,1.425) 6(-1.24,-1.425) 10(1.24,-1.425) 15(1.24,1.425)
  rrect50% 0.2x2.24 smd mask+0.05: 7(-0.45,-0.6) 9(0.45,-0.6)
  rrect50% 0.2x0.7 smd mask+0.05: 8(0,-1.375)
  rrect50% 0.2x0.6 smd mask+0.05: 16(0.65,1.425) 18(-0.65,1.425)
  rrect50% 0.2x2.25 smd mask+0.05: 17(0,0.6)
Top Overlay:
  text "1" at -2.225,1.075 h1.3
M14-Top Assembly:
  lines w0.01: -1.5,-1.375 -1.375,-1.375 -1.375,-1.5 ; -1.5,-1.125 -1.475,-1.125 -1.2,-1.125 cw(c-1.2,-1.225) -1.1,-1.225 -1.1,-1.5 ; -1.5,-0.875 -1.225,-0.875 ccw(c-1.225,-0.75) -1.1,-0.75 ccw(c-1.225,-0.75) -1.225,-0.625 -1.5,-0.625 ; -1.5,-0.375 -1.225,-0.375 ccw(c-1.225,-0.25) -1.1,-0.25 ccw(c-1.225,-0.25) -1.225,-0.125 -1.5,-0.125 ; -1.5,0.125 -1.225,0.125 ccw(c-1.225,0.25) -1.1,0.25 ccw(c-1.225,0.25) -1.225,0.375 -1.5,0.375 ; -1.5,0.625 -1.225,0.625 ccw(c-1.225,0.75) -1.1,0.75 ccw(c-1.225,0.75) -1.225,0.875 -1.5,0.875 ; -1.5,1.125 -1.475,1.125 -1.2,1.125 -1.1,1.225 -1.1,1.5 -1.5,1.5 ; -1.5,1.375 -1.375,1.375 -1.375,1.5 ; -0.75,1.5 -0.75,1.225 ccw(c-0.65,1.225) -0.65,1.125 ccw(c-0.65,1.225) -0.55,1.225 -0.55,1.5 ; -0.55,-1.5 -0.55,0.5 -0.35,0.5 -0.35,-1.5 ; -0.1,-1.5 -0.1,-1 0.1,-1 0.1,-1.5 ; -0.1,1.5 -0.1,-0.5 0.1,-0.5 0.1,1.5 ; 0.35,-1.5 0.35,0.5 0.55,0.5 0.55,-1.5 ; 0.55,1.5 0.55,1.225 ccw(c0.65,1.225) 0.65,1.125 ccw(c0.65,1.225) 0.75,1.225 0.75,1.5 ; 1.1,-1.5 1.1,-1.225 cw(c1.2,-1.225) 1.2,-1.125 1.475,-1.125 1.5,-1.125 ; 1.1,1.5 1.1,1.225 ccw(c1.2,1.225) 1.2,1.125 1.475,1.125 1.5,1.125 ; 1.375,-1.5 1.375,-1.375 1.5,-1.375 ; 1.375,1.5 1.375,1.375 1.5,1.375 ; 1.5,-0.875 1.225,-0.875 cw(c1.225,-0.75) 1.1,-0.75 cw(c1.225,-0.75) 1.225,-0.625 1.5,-0.625 ; 1.5,-0.375 1.225,-0.375 cw(c1.225,-0.25) 1.1,-0.25 cw(c1.225,-0.25) 1.225,-0.125 1.5,-0.125 ; 1.5,0.125 1.225,0.125 cw(c1.225,0.25) 1.1,0.25 cw(c1.225,0.25) 1.225,0.375 1.5,0.375 ; 1.5,0.625 1.225,0.625 cw(c1.225,0.75) 1.1,0.75 cw(c1.225,0.75) 1.225,0.875 1.5,0.875 ; -1.5,1.5 -1.5,-1.5 1.5,-1.5 1.5,1.5 -1.5,1.5
  text "18" at -0.825,1.175 h0.4
  text "16" at 0.475,1.2 h0.4
  text "9" at 0.375,-1.45 h0.4
  text "7" at -0.525,-1.45 h0.4
  text "'.Designator'" at -2,-0.5 h0.75
  text "15" at 1.125,1.175 h0.4
  text "10" at 1.15,-1.425 h0.4
  text "6" at -1.4,-1.45 h0.4
  text "1" at -1.35,1.2 h0.4
M16-Top Courtyard:
  lines w0.01: -1.85,-1.875 -1.85,1.875 1.85,1.875 1.85,-1.875 -1.85,-1.875
3D body: height 1, standoff 0, extent -1.5,-1.5 1.5,1.5

## ICC_VQFN24-EPAD_4X4_P050 [mm]
height 1
pads (25):
  rrect50% 0.85x0.3 smd mask+0.05: 1(-1.95,1.25) 2(-1.95,0.75) 3(-1.95,0.25) 4(-1.95,-0.25) 5(-1.95,-0.75) 6(-1.95,-1.25) 13(1.95,-1.25) 14(1.95,-0.75) 15(1.95,-0.25) 16(1.95,0.25) 17(1.95,0.75) 18(1.95,1.25)
  rrect50% 0.3x0.85 smd mask+0.05: 7(-1.25,-1.95) 8(-0.75,-1.95) 9(-0.25,-1.95) 10(0.25,-1.95) 11(0.75,-1.95) 12(1.25,-1.95) 19(1.25,1.95) 20(0.75,1.95) 21(0.25,1.95) 22(-0.25,1.95) 23(-0.75,1.95) 24(-1.25,1.95)
  rect 2.6x2.6 smd paste-10 mask+0.05: EP(0,0)
via 0,0 diameter 0.6 hole 0.3
via -1,0 diameter 0.6 hole 0.3
via -1,1 diameter 0.6 hole 0.3
via 0,1 diameter 0.6 hole 0.3
via 1,1 diameter 0.6 hole 0.3
via 1,0 diameter 0.6 hole 0.3
via 1,-1 diameter 0.6 hole 0.3
via 0,-1 diameter 0.6 hole 0.3
via -1,-1 diameter 0.6 hole 0.3
Top Overlay:
  circle w0.254: c-1.7,1.7 r0.075
  lines w0.12: -2,-1.525 -2,-2 -1.525,-2 ; -2,1.525 -2,2 -1.525,2 ; 1.525,-2 2,-2 2,-1.525 ; 1.525,2 2,2 2,1.525
  text "1" at -2.475,1.5 h1.5
Top Paste:
  rectangle: -0.875,-0.875 -0.125,-0.125
  rectangle: 0.125,-0.875 0.875,-0.125
  rectangle: 0.125,0.125 0.875,0.875
  rectangle: -0.875,0.125 -0.125,0.875
M14-Top Assembly:
  lines w0.01: -2,-1.4 -1.55,-1.4 -1.55,-1.1 -2,-1.1 ; -2,-0.9 -1.55,-0.9 -1.55,-0.6 -2,-0.6 ; -2,-0.4 -1.55,-0.4 -1.55,-0.1 -2,-0.1 ; -2,0.1 -1.55,0.1 -1.55,0.4 -2,0.4 ; -2,0.6 -1.55,0.6 -1.55,0.9 -2,0.9 ; -2,1.1 -1.55,1.1 -1.55,1.4 -2,1.4 ; -1.4,-2 -1.4,-1.55 -1.1,-1.55 -1.1,-2 ; -1.4,2 -1.4,1.55 -1.1,1.55 -1.1,2 ; -0.9,-2 -0.9,-1.55 -0.6,-1.55 -0.6,-2 ; -0.9,2 -0.9,1.55 -0.6,1.55 -0.6,2 ; -0.4,-2 -0.4,-1.55 -0.1,-1.55 -0.1,-2 ; -0.4,2 -0.4,1.55 -0.1,1.55 -0.1,2 ; 0.1,-2 0.1,-1.55 0.4,-1.55 0.4,-2 ; 0.1,2 0.1,1.55 0.4,1.55 0.4,2 ; 0.6,-2 0.6,-1.55 0.9,-1.55 0.9,-2 ; 0.6,2 0.6,1.55 0.9,1.55 0.9,2 ; 1.1,-2 1.1,-1.55 1.4,-1.55 1.4,-2 ; 1.1,2 1.1,1.55 1.4,1.55 1.4,2 ; 2,-1.4 1.55,-1.4 1.55,-1.1 2,-1.1 ; 2,-0.9 1.55,-0.9 1.55,-0.6 2,-0.6 ; 2,-0.4 1.55,-0.4 1.55,-0.1 2,-0.1 ; 2,0.1 1.55,0.1 1.55,0.4 2,0.4 ; 2,0.6 1.55,0.6 1.55,0.9 2,0.9 ; 2,1.1 1.55,1.1 1.55,1.4 2,1.4 ; -2,-2 -2,2 2,2 2,-2 -2,-2 ; -1.25,-1.25 1.25,-1.25 1.25,1.25 -1.25,1.25 -1.25,-1.25
  text "'.Designator'" at -2,0.25 h0.75
  text "6" at -2.45,-1.125 h0.65
  text "24" at -1.575,2.05 h0.65
  text "19" at 0.975,2.05 h0.65
  text "18" at 2.45,0.975 h0.65
  text "13" at 2.45,-1.525 h0.65
  text "12" at 0.975,-2.45 h0.65
  text "7" at -1.4,-2.45 h0.65
  text "1" at -2.475,1.325 h0.65
  text "25" at -0.3,-0.225 h0.65
M16-Top Courtyard:
  lines w0.01: -2.525,-2.525 2.525,-2.525 2.525,2.525 -2.525,2.525 -2.525,-2.525
3D body "VQFN24-EPAD.STEP": height 1.05, standoff -0.03, extent -2.05,-2.05 2.05,2.05
3D body: height 1.1, standoff 1, extent -1.448,1.051 -1.05,1.45
3D body: height 1, standoff 0, extent -2,-2 2,2

## ICC_VQFN56-EPAD_8X8_P050 [mm] "MCD-02356"
height 0.9
pads (57):
  rrect80% 0.3x0.3 smd mask+0.05: 1(-3.8,3.25) 14(-3.8,-3.25) 15(-3.25,-3.8) 28(3.25,-3.8) 29(3.8,-3.25) 42(3.8,3.25) 43(3.25,3.8) 56(-3.25,3.8)
  rect 1x0.3 smd mask+0.05: 2(-3.8,2.75) 3(-3.8,2.25) 4(-3.8,1.75) 5(-3.8,1.25) 6(-3.8,0.75) 7(-3.8,0.25) 8(-3.8,-0.25) 9(-3.8,-0.75) 10(-3.8,-1.25) 11(-3.8,-1.75) 12(-3.8,-2.25) 13(-3.8,-2.75) 30(3.8,-2.75) 31(3.8,-2.25) 32(3.8,-1.75) 33(3.8,-1.25) 34(3.8,-0.75) 35(3.8,-0.25) 36(3.8,0.25) 37(3.8,0.75) 38(3.8,1.25) 39(3.8,1.75) 40(3.8,2.25) 41(3.8,2.75)
  rect 0.3x1 smd mask+0.05: 16(-2.75,-3.8) 17(-2.25,-3.8) 18(-1.75,-3.8) 19(-1.25,-3.8) 20(-0.75,-3.8) 21(-0.25,-3.8) 22(0.25,-3.8) 23(0.75,-3.8) 24(1.25,-3.8) 25(1.75,-3.8) 26(2.25,-3.8) 27(2.75,-3.8) 44(2.75,3.8) 45(2.25,3.8) 46(1.75,3.8) 47(1.25,3.8) 48(0.75,3.8) 49(0.25,3.8) 50(-0.25,3.8) 51(-0.75,3.8) 52(-1.25,3.8) 53(-1.75,3.8) 54(-2.25,3.8) 55(-2.75,3.8)
  rect 6.2x6.2 smd mask+0.05: 57(0,0)
Top Layer:
  region: -4.3,-3.4 -3.541,-3.4 -3.3,-3.159 -3.3,-3.1 -4.3,-3.1
  region: -4.3,3.4 -3.541,3.4 -3.3,3.159 -3.3,3.1 -4.3,3.1
  region: 3.4,-4.3 3.4,-3.541 3.159,-3.3 3.1,-3.3 3.1,-4.3
  region: -3.4,-4.3 -3.4,-3.541 -3.159,-3.3 -3.1,-3.3 -3.1,-4.3
  region: 4.3,3.4 3.541,3.4 3.3,3.159 3.3,3.1 4.3,3.1
  region: 4.3,-3.4 3.541,-3.4 3.3,-3.159 3.3,-3.1 4.3,-3.1
  region: -3.4,4.3 -3.4,3.541 -3.159,3.3 -3.1,3.3 -3.1,4.3
  region: 3.4,4.3 3.4,3.541 3.159,3.3 3.1,3.3 3.1,4.3
Top Overlay:
  lines w0.12: -4.375,3.525 -4.375,4.375 -3.525,4.375 ; -4,-3.525 -4,-4 -3.525,-4 ; -4,3.525 -4,4 -3.525,4 ; 3.525,-4 4,-4 4,-3.525 ; 3.525,4 4,4 4,3.525
M14-Top Assembly:
  drawing of 184 lines, arcs and shapes, not listed
  text "57" at -0.275,-0.168 h0.6
  text "56" at -3.525,3.582 h0.6
  text "43" at 2.975,3.557 h0.6
  text "42" at 3.393,3.05 h0.6
  text "29" at 3.374,-3.443 h0.6
  text "28" at 2.974,-3.943 h0.6
  text "15" at -3.525,-3.943 h0.6
  text "14" at -3.95,-3.45 h0.6
  text "1" at -3.95,3 h0.8
  text "'.Designator'" at -2,1 h0.75
M16-Top Courtyard:
  lines w0.01: -4.45,-4.45 -4.45,4.45 4.45,4.45 4.45,-4.45 -4.45,-4.45
3D body "VQFN_56.STEP": height 1.1, standoff 0, extent -4,-4 4,4

## ICC_VSON8-EPAD_3X3_P065 [mm] "MCD-02727"
height 1
pads (9):
  rect 0.6x0.35 smd paste+0 mask+0.05: 1(-1.4,0.975) 2(-1.4,0.325) 3(-1.4,-0.325) 4(-1.4,-0.975) 5(1.4,-0.975) 6(1.4,-0.325) 7(1.4,0.325) 8(1.4,0.975)
  rect 1.5x1.75 smd paste+0 mask+0.05: 9(0,0)
Top Layer:
  region: -0.75,0.875 -0.45,0.875 -0.45,1.7 -0.2,1.7 -0.2,0.875 0.2,0.875 0.2,1.7 0.45,1.7 0.45,0.875 0.75,0.875 0.75,-0.875 0.45,-0.875 0.45,-1.7 0.2,-1.7 0.2,-0.875 -0.2,-0.875 -0.2,-1.7 -0.45,-1.7 -0.45,-0.875 -0.75,-0.875
Top Overlay:
  lines w0.12: -1.55,-1.325 -1.55,-1.55 -0.625,-1.55 ; -1.55,1.325 -1.55,1.55 -0.625,1.55 ; 0.625,-1.55 1.55,-1.55 1.55,-1.325 ; 0.625,1.55 1.55,1.55 1.55,1.325
  text "1" at -2.075,0.825 h1.3
M14-Top Assembly:
  lines w0.01: -1.55,-1.125 -1.05,-1.125 -1.05,-0.825 -1.55,-0.825 ; -1.55,-0.475 -1.05,-0.475 -1.05,-0.175 -1.55,-0.175 ; -1.55,0.175 -1.05,0.175 -1.05,0.475 -1.55,0.475 ; -1.55,0.825 -1.05,0.825 -1.05,1.125 -1.55,1.125 ; -0.45,-1.55 -0.45,-0.875 -0.75,-0.875 -0.75,0.875 ; -0.45,1.55 -0.45,0.875 -0.75,0.875 ; -0.2,-1.55 -0.2,-0.875 0.2,-0.875 0.2,-1.55 ; -0.2,1.55 -0.2,0.875 0.2,0.875 0.2,1.55 ; 0.45,-1.55 0.45,-0.875 0.75,-0.875 ; 0.45,1.55 0.45,0.875 0.75,0.875 0.75,-0.875 ; 1.55,-1.125 1.05,-1.125 1.05,-0.825 1.55,-0.825 ; 1.55,-0.475 1.05,-0.475 1.05,-0.175 1.55,-0.175 ; 1.55,0.175 1.05,0.175 1.05,0.475 1.55,0.475 ; 1.55,0.825 1.05,0.825 1.05,1.125 1.55,1.125 ; -0.75,0.875 -0.75,0.875 ; 0.75,-0.875 0.75,-0.875 ; -1.55,-1.55 1.55,-1.55 1.55,1.55 -1.55,1.55 -1.55,-1.55
  text "8" at 1.175,0.825 h0.5
  text "5" at 1.2,-1.125 h0.5
  text "4" at -1.45,-1.125 h0.5
  text "1" at -1.4,0.825 h0.5
  text "'.Designator'" at -2,-0.5 h0.75
  text "EP" at -0.275,-0.125 h0.5
M16-Top Courtyard:
  lines w0.01: 4.45,-3.25 4.45,-3.225 ; -1.85,-1.85 -1.85,1.85 1.85,1.85 1.85,-1.85 -1.85,-1.85
3D body "User Library-VSON_8_3x3_e0p65.STEP": height 1, standoff 0, extent -1.5,-1.5 1.5,1.5

## ICC_VSSOP8_DCU_R-PDSO-G8_2X2P30_P050 [mm]
height 0.9
pads (8):
  rect 0.3x0.8 smd mask+0.05: 1(-0.75,-1.55) 2(-0.25,-1.55) 3(0.25,-1.55) 4(0.75,-1.55) 5(0.75,1.55) 6(0.25,1.55) 7(-0.25,1.55) 8(-0.75,1.55)
Top Overlay:
  circle w0.12: c-0.75,-0.875 r0.15
  lines w0.12: -1.025,-1.2 -1.05,-1.2 -1.05,1.2 -1.025,1.2 ; 1.025,-1.2 1.05,-1.2 1.05,1.2 1.025,1.2
  text "1" at -1.325,-2.15 h1.3
M14-Top Assembly:
  circle w0.01: c-0.75,-0.875 r0.2
  lines w0.01: -0.85,-1.2 -0.85,-1.6 -0.65,-1.6 -0.65,-1.2 ; -0.85,1.2 -0.85,1.6 -0.65,1.6 -0.65,1.2 ; -0.35,-1.2 -0.35,-1.6 -0.15,-1.6 -0.15,-1.2 ; -0.35,1.2 -0.35,1.6 -0.15,1.6 -0.15,1.2 ; 0.15,-1.2 0.15,-1.6 0.35,-1.6 0.35,-1.2 ; 0.15,1.2 0.15,1.6 0.35,1.6 0.35,1.2 ; 0.65,-1.2 0.65,-1.6 0.85,-1.6 0.85,-1.2 ; 0.65,1.2 0.65,1.6 0.85,1.6 0.85,1.2 ; -1.05,-1.2 1.05,-1.2 1.05,1.2 -1.05,1.2 -1.05,-1.2
  text "1" at -0.875,-1.8 h0.75
  text "4" at 0.575,-1.8 h0.75
  text "8" at -0.9,1.3 h0.75
  text "5" at 0.6,1.3 h0.75
  text "'.Designator'" at -2,-0.5 h0.75
M16-Top Courtyard:
  lines w0.01: -1.25,-2.1 -1.25,2.1 1.25,2.1 1.25,-2.1 -1.25,-2.1
3D body "DCU8.stp": height 0.89, standoff 0, extent -1.054,-1.624 1.054,1.624
3D body: height 0.9, standoff 0, extent -1.049,-1.199 1.049,1.199

## ICC_VSSOP8_DGK_S-PDSO-G8_3X3_P065 [mm]
height 1.1
pads (8):
  rect 0.45x1.45 smd mask+0.05: 1(-0.975,-2.2) 2(-0.325,-2.2) 3(0.325,-2.2) 4(0.975,-2.2) 5(0.975,2.2) 6(0.325,2.2) 7(-0.325,2.2) 8(-0.975,2.2)
Top Overlay:
  circle w0.12: c-1.125,-1.125 r0.225
  lines w0.12: -1.325,-1.55 -1.55,-1.55 -1.55,1.55 -1.325,1.55 ; 1.325,-1.55 1.55,-1.55 1.55,1.55 1.325,1.55
  text "1" at -1.675,-2.7 h1.5
M14-Top Assembly:
  circle w0.01: c-1.125,-1.125 r0.25
  lines w0.01: -1.175,-1.55 -1.175,-2.55 -0.775,-2.55 -0.775,-1.55 ; -1.175,1.55 -1.175,2.55 -0.775,2.55 -0.775,1.55 ; -0.525,-1.55 -0.525,-2.55 -0.125,-2.55 -0.125,-1.55 ; -0.525,1.55 -0.525,2.55 -0.125,2.55 -0.125,1.55 ; 0.125,-1.55 0.125,-2.55 0.525,-2.55 0.525,-1.55 ; 0.125,1.55 0.125,2.55 0.525,2.55 0.525,1.55 ; 0.775,-1.55 0.775,-2.55 1.175,-2.55 1.175,-1.55 ; 0.775,1.55 0.775,2.55 1.175,2.55 1.175,1.55 ; -1.55,-1.55 1.55,-1.55 1.55,1.55 -1.55,1.55 -1.55,-1.55
  text "1" at -1.1,-2.4 h1
  text "4" at 0.75,-2.375 h1
  text "8" at -1.2,1.725 h1
  text "5" at 0.775,1.725 h1
  text "'.Designator'" at -2,-0.5 h0.75
M16-Top Courtyard:
  lines w0.01: -1.75,-3.075 -1.75,3.075 1.75,3.075 1.75,-3.075 -1.75,-3.075
3D body: height 1.11, standoff 1.1, extent -1.373,-1.374 -0.875,-0.875
3D body: height 1.1, standoff 0, extent -1.55,-1.55 1.55,1.55
3D body "VSSOP8-3X3_P065.STEP": height 0.96, standoff 0, extent -1.5,-2.45 1.5,2.45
